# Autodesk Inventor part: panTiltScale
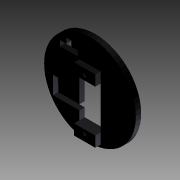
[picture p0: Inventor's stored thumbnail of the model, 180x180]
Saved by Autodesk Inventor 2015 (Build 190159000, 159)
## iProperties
Created: 2015-02
Part Number: panTiltScale
Material: Generic
Document SubType Name: Modeling
Designer: sungeun
Density: 1 g/cm^3
Appearance: Default
Author: sungeun
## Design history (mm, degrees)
feature "panTilt"
feature "MeshFeature1"
body "Solid1"
